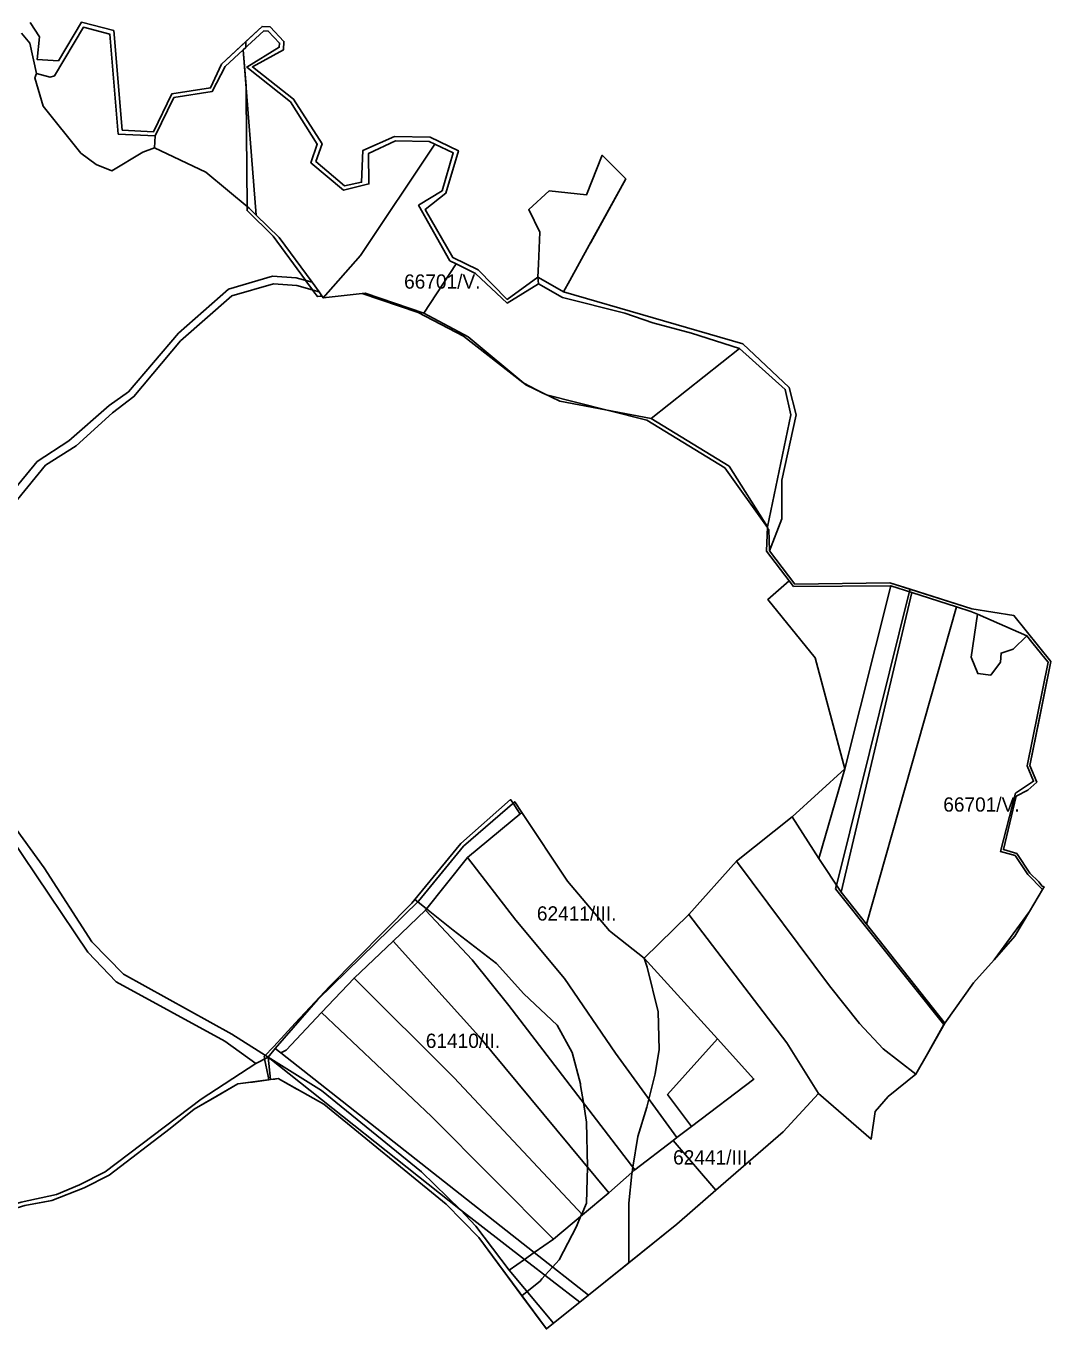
# Model space of a CAD drawing. Extents: x -522079 to -518833, y -1142400 to -1139961.
# Drawn here: x -519191.9 to -518832.8, y -1141827.7 to -1141371.1 of the extents above; entities that cross this region are included whole.
import ezdxf

# ---------------------------------------------------------------- set-up
doc = ezdxf.new("R2010")
doc.units = 0
for name, color, linetype in [('95560013', 7, 'Continuous'), ('95610013', 7, 'Continuous'), ('95620013', 7, 'Continuous'), ('95630013', 7, 'Continuous'), ('95640013', 7, 'Continuous'), ('95660013', 7, 'Continuous')]:
    doc.layers.add(name, color=color, linetype=linetype)

msp = doc.modelspace()

# ---------------------------------------------------------------- linework, layer by layer
at = {"layer": '95560013'}
for points in [[(-519037.2, -1141662.52), (-519020.32, -1141684.47), (-519003.26, -1141704.92), (-518985.35, -1141731.05), (-518963.82, -1141760.65), (-518965.15, -1141761.66), (-518978.59, -1141771.9), (-519022.75, -1141714.32), (-519035.63, -1141698.35), (-519051.93, -1141680.89)], [(-518978.59, -1141771.9), (-518987.69, -1141779.96), (-519033.2, -1141725.1), (-519063.3, -1141691.75), (-519051.93, -1141680.89), (-519035.63, -1141698.35), (-519022.75, -1141714.32)], [(-519063.3, -1141691.75), (-519033.2, -1141725.1), (-518987.69, -1141779.96), (-518996.96, -1141787.68), (-519041.86, -1141739.72), (-519076.93, -1141704.76)], [(-519076.93, -1141704.76), (-519041.86, -1141739.72), (-518996.96, -1141787.68), (-519007.07, -1141796.21), (-519049.77, -1141753.31), (-519088.31, -1141716.77)], [(-519100.73, -1141730.04), (-519088.31, -1141716.77), (-519049.77, -1141753.31), (-519007.07, -1141796.21), (-519013.82, -1141800.95), (-519102.66, -1141730.9)], [(-519034.33, -1141791.67), (-519022.6, -1141807.12), (-519007.06, -1141825.69), (-519009.58, -1141827.71), (-519033.21, -1141795.69), (-519044.72, -1141783.93), (-519087.6, -1141748.94), (-519103.5, -1141739.96), (-519106.29, -1141740.33), (-519107.07, -1141732.42), (-519039.72, -1141785.92)], [(-518978.59, -1141771.9), (-518965.15, -1141761.66), (-518950.14, -1141779.05), (-518963.91, -1141791), (-518994.87, -1141815.89), (-519013.82, -1141800.95), (-519007.07, -1141796.21), (-518996.96, -1141787.68), (-518987.69, -1141779.96)], [(-519039.72, -1141785.92), (-519017.2, -1141803.32), (-519022.6, -1141807.12), (-519034.33, -1141791.67)], [(-519022.6, -1141807.12), (-519017.2, -1141803.32), (-518997.83, -1141818.27), (-519007.06, -1141825.69)]]:
    msp.add_lwpolyline(points, close=True, dxfattribs=at)
at = {"layer": '95610013'}
for points in [[(-519012.53, -1141459.04), (-519012.34, -1141454.52), (-519011.87, -1141443.33), (-519015.74, -1141435.38), (-519008.63, -1141428.83), (-518995.53, -1141430.25), (-518989.97, -1141416.33), (-518981.74, -1141424.63), (-518994.55, -1141447.83), (-519001.41, -1141460.26), (-519003.59, -1141464.2), (-519005.83, -1141462.95)], [(-518906.3, -1141674.57), (-518881.49, -1141569.59), (-518865.88, -1141574.59), (-518897.41, -1141685.82)], [(-518845.18, -1141639.97), (-518850.48, -1141660.34), (-518845.32, -1141661.82), (-518840.87, -1141668.48), (-518835.69, -1141673.66), (-518840.27, -1141681.38), (-518852.72, -1141698.29), (-518859.88, -1141706.38), (-518869.99, -1141720.5), (-518897.41, -1141685.82), (-518865.88, -1141574.59), (-518860.8, -1141576.22), (-518858.5, -1141577.22), (-518860.72, -1141592.27), (-518858.42, -1141598.04), (-518853.84, -1141598.54), (-518850.43, -1141594.07), (-518850.24, -1141590.84), (-518845.96, -1141589.42), (-518841.19, -1141584.77), (-518839.43, -1141586.95), (-518834.47, -1141593.24), (-518833.75, -1141593.98), (-518841.11, -1141630.32), (-518838.85, -1141635.75)], [(-518853.84, -1141598.54), (-518858.42, -1141598.04), (-518860.72, -1141592.27), (-518858.5, -1141577.22), (-518841.19, -1141584.77), (-518845.96, -1141589.42), (-518850.24, -1141590.84), (-518850.43, -1141594.07)], [(-519037.2, -1141662.52), (-519018.14, -1141646.74), (-519002.22, -1141670.75), (-518987.45, -1141688.21), (-518975.25, -1141697.8), (-518949.63, -1141726.06), (-518967.09, -1141745.55), (-518958.75, -1141756.79), (-518963.82, -1141760.65), (-518985.35, -1141731.05), (-519003.26, -1141704.92), (-519020.32, -1141684.47)], [(-518845.39, -1141690.02), (-518852.72, -1141698.29), (-518840.27, -1141681.38)]]:
    msp.add_lwpolyline(points, close=True, dxfattribs=at)
at = {"layer": '95620013'}
for points in [[(-519193.48, -1141373.59), (-519190.53, -1141377.07), (-519188.19, -1141387.74), (-519188.81, -1141389.21), (-519185.95, -1141399.11), (-519172.73, -1141415.6), (-519167.27, -1141419.59), (-519161.79, -1141421.83), (-519150.96, -1141415.24), (-519146.88, -1141413.75), (-519128.84, -1141422.33), (-519113.73, -1141434.94), (-519111.28, -1141437.32), (-519103.24, -1141445.12), (-519091.6, -1141460.78), (-519097.28, -1141459.27), (-519105.52, -1141458.68), (-519120.93, -1141463.32), (-519138.46, -1141478.73), (-519156, -1141499.24), (-519162.77, -1141504.09), (-519176.92, -1141516.46), (-519187.98, -1141523.67), (-519197.16, -1141534.83)], [(-519194.87, -1141536.97), (-519185.11, -1141524.98), (-519174.38, -1141518.14), (-519161.65, -1141506.59), (-519154.09, -1141500.95), (-519137.74, -1141481.36), (-519119.76, -1141465.66), (-519105.2, -1141461.4), (-519097.02, -1141461.95), (-519089.22, -1141464.23), (-519087.76, -1141466.33), (-519073.04, -1141464.69), (-519052.51, -1141471.71), (-519036.96, -1141480), (-519016.8, -1141496.81), (-519004.9, -1141502.52), (-518972.83, -1141508.64), (-518945.58, -1141525.34), (-518932.13, -1141546.59), (-518932.45, -1141555.15), (-518924.52, -1141565.49), (-518931.99, -1141572.05), (-518915.44, -1141592.52), (-518904.97, -1141631.37), (-518923.48, -1141648.24), (-518942.97, -1141663.76), (-518959.67, -1141682.43), (-518975.25, -1141697.8), (-518987.45, -1141688.21), (-519002.22, -1141670.75), (-519018.14, -1141646.74), (-519020.66, -1141642.94), (-519038.58, -1141658.51), (-519054.42, -1141677.83), (-519089.65, -1141712.19), (-519104.58, -1141729.38), (-519107.07, -1141732.42), (-519119.77, -1141724.36), (-519157.76, -1141703.36), (-519168.83, -1141692.07), (-519185.55, -1141666.07), (-519195.4, -1141652.58)], [(-519197.57, -1141654.98), (-519170.28, -1141695.6), (-519160.32, -1141706.01), (-519122.24, -1141726.88), (-519111.34, -1141734.71), (-519130.56, -1141747.22), (-519164.17, -1141772.59), (-519173.18, -1141777.23), (-519181.21, -1141780.54), (-519193.63, -1141783.33)]]:
    msp.add_lwpolyline(points, dxfattribs=at)
for points in [[(-519167.27, -1141419.59), (-519172.73, -1141415.6), (-519185.95, -1141399.11), (-519188.81, -1141389.21), (-519188.19, -1141387.74), (-519183.39, -1141388.93), (-519181.87, -1141388.46), (-519171.77, -1141371.48), (-519162.56, -1141373.86), (-519159.57, -1141408.94), (-519146.7, -1141409.56), (-519146.88, -1141413.75), (-519150.96, -1141415.24), (-519161.79, -1141421.83)], [(-519115.78, -1141379.37), (-519108.63, -1141372.74), (-519107.04, -1141372.83), (-519103.08, -1141377.03), (-519103.16, -1141378.52), (-519114.56, -1141385.44), (-519099.25, -1141397.67), (-519089.83, -1141412.51), (-519092.08, -1141418.96), (-519080.67, -1141428.64), (-519071.77, -1141426.39), (-519071.92, -1141415.76), (-519062.49, -1141411.31), (-519050.68, -1141411.48), (-519048.65, -1141412.42), (-519074.76, -1141451.52), (-519087.76, -1141466.33), (-519089.22, -1141464.23), (-519091.6, -1141460.78), (-519103.24, -1141445.12), (-519111.28, -1141437.32)], [(-519113.73, -1141434.94), (-519128.84, -1141422.33), (-519146.88, -1141413.75), (-519146.7, -1141409.56), (-519140.08, -1141396.13), (-519126.66, -1141393.95), (-519122.09, -1141385.22), (-519115.78, -1141379.37), (-519111.28, -1141437.32)], [(-519048.65, -1141412.42), (-519042.19, -1141415.54), (-519046.13, -1141428.81), (-519054.33, -1141433.88), (-519043.38, -1141453.33), (-519041.21, -1141454.39), (-519052.51, -1141471.71), (-519073.04, -1141464.69), (-519087.76, -1141466.33), (-519074.76, -1141451.52)], [(-518941.87, -1141484.11), (-518972.83, -1141508.64), (-519004.9, -1141502.52), (-519016.8, -1141496.81), (-519036.96, -1141480), (-519052.51, -1141471.71), (-519041.21, -1141454.39), (-519034.35, -1141457.76), (-519023.36, -1141468.17), (-519012.3, -1141461.46), (-519003.93, -1141466.26), (-518982.13, -1141471.67), (-518972.22, -1141475.1), (-518958.68, -1141478.71)], [(-518932.13, -1141546.59), (-518945.58, -1141525.34), (-518972.83, -1141508.64), (-518941.87, -1141484.11), (-518925.88, -1141498.42), (-518923.9, -1141507.34)], [(-518888.92, -1141567.21), (-518904.97, -1141631.37), (-518915.44, -1141592.52), (-518931.99, -1141572.05), (-518924.52, -1141565.49), (-518922.95, -1141567.54)], [(-518906.3, -1141674.57), (-518914.15, -1141662.84), (-518904.97, -1141631.37), (-518888.92, -1141567.21), (-518881.49, -1141569.59)], [(-518904.97, -1141631.37), (-518914.15, -1141662.84), (-518923.48, -1141648.24)], [(-518942.97, -1141663.76), (-518923.48, -1141648.24), (-518914.15, -1141662.84), (-518906.3, -1141674.57), (-518897.41, -1141685.82), (-518869.99, -1141720.5), (-518876.08, -1141731.29), (-518880.1, -1141738.42), (-518891.54, -1141729.55), (-518899.83, -1141720.66), (-518910.37, -1141707.51)], [(-518925.33, -1141727.39), (-518959.67, -1141682.43), (-518942.97, -1141663.76), (-518910.37, -1141707.51), (-518899.83, -1141720.66), (-518891.54, -1141729.55), (-518880.1, -1141738.42), (-518889.83, -1141746.28), (-518894.38, -1141751.49), (-518895.73, -1141761.19), (-518914.26, -1141745.22)], [(-518965.15, -1141761.66), (-518963.82, -1141760.65), (-518958.75, -1141756.79), (-518936.87, -1141740.13), (-518949.63, -1141726.06), (-518975.25, -1141697.8), (-518959.67, -1141682.43), (-518925.33, -1141727.39), (-518914.26, -1141745.22), (-518926.6, -1141758.63), (-518950.14, -1141779.05)], [(-518958.75, -1141756.79), (-518967.09, -1141745.55), (-518949.63, -1141726.06), (-518936.87, -1141740.13)]]:
    msp.add_lwpolyline(points, close=True, dxfattribs=at)
at = {"layer": '95630013'}
msp.add_lwpolyline([(-519190.42, -1141369.81), (-519187.2, -1141374.82), (-519188.01, -1141382.78), (-519180.54, -1141383.29), (-519172.49, -1141369.75), (-519161.16, -1141372.68), (-519158.19, -1141407.51), (-519147.23, -1141408.12), (-519140.85, -1141394.82), (-519127.25, -1141392.73), (-519123.4, -1141384.39), (-519109.18, -1141371.2), (-519106.36, -1141371.37), (-519101.55, -1141376.47), (-519101.7, -1141379.43), (-519112.59, -1141385.36), (-519098.12, -1141396.65), (-519088.18, -1141412.32), (-519090.32, -1141418.48), (-519080.26, -1141427.02), (-519074.35, -1141425.83), (-519073.85, -1141414.66), (-519062.78, -1141409.81), (-519050.33, -1141409.98), (-519040.39, -1141414.74), (-519044.82, -1141429.69), (-519052, -1141435.32), (-519042.3, -1141452.19), (-519033.46, -1141456.53), (-519023.29, -1141466.86), (-519012.53, -1141459.04), (-519012.3, -1141461.46), (-519023.36, -1141468.17), (-519034.35, -1141457.76), (-519041.21, -1141454.39), (-519043.38, -1141453.33), (-519054.33, -1141433.88), (-519046.13, -1141428.81), (-519042.19, -1141415.54), (-519048.65, -1141412.42), (-519050.68, -1141411.48), (-519062.49, -1141411.31), (-519071.92, -1141415.76), (-519071.77, -1141426.39), (-519080.67, -1141428.64), (-519092.08, -1141418.96), (-519089.83, -1141412.51), (-519099.25, -1141397.67), (-519114.56, -1141385.44), (-519103.16, -1141378.52), (-519103.08, -1141377.03), (-519107.04, -1141372.83), (-519108.63, -1141372.74), (-519115.78, -1141379.37), (-519122.09, -1141385.22), (-519126.66, -1141393.95), (-519140.08, -1141396.13), (-519146.7, -1141409.56), (-519159.57, -1141408.94), (-519162.56, -1141373.86), (-519171.77, -1141371.48), (-519181.87, -1141388.46), (-519183.39, -1141388.93), (-519188.19, -1141387.74), (-519190.53, -1141377.07), (-519193.48, -1141373.59)], dxfattribs=at)
msp.add_lwpolyline([(-518841.19, -1141584.77), (-518858.5, -1141577.22), (-518860.8, -1141576.22), (-518865.88, -1141574.59), (-518881.49, -1141569.59), (-518888.92, -1141567.21), (-518922.95, -1141567.54), (-518924.52, -1141565.49), (-518932.45, -1141555.15), (-518932.13, -1141546.59), (-518923.9, -1141507.34), (-518925.88, -1141498.42), (-518941.87, -1141484.11), (-518958.68, -1141478.71), (-518972.22, -1141475.1), (-518982.13, -1141471.67), (-519003.93, -1141466.26), (-519012.3, -1141461.46), (-519012.53, -1141459.04), (-519005.83, -1141462.95), (-519003.59, -1141464.2), (-518940.71, -1141482.48), (-518924.49, -1141497.8), (-518922.06, -1141507.35), (-518927.02, -1141530.23), (-518927.11, -1141543.74), (-518931.43, -1141555), (-518922.51, -1141566.63), (-518889.18, -1141566.18), (-518860.53, -1141575.36), (-518845.76, -1141577.71), (-518832.78, -1141593.74), (-518840.17, -1141630.23), (-518837.74, -1141636.08), (-518840.9, -1141638.87), (-518844.96, -1141640.98), (-518849.41, -1141659.71), (-518844.75, -1141661.05), (-518840.16, -1141667.91), (-518837.05, -1141671.02), (-518835.83, -1141672.48), (-518835.18, -1141672.79), (-518835.69, -1141673.66), (-518840.87, -1141668.48), (-518845.32, -1141661.82), (-518850.48, -1141660.34), (-518845.18, -1141639.97), (-518838.85, -1141635.75), (-518841.11, -1141630.32), (-518833.75, -1141593.98), (-518834.47, -1141593.24), (-518839.43, -1141586.95)], close=True, dxfattribs=at)
at = {"layer": '95640013'}
msp.add_lwpolyline([(-519197.16, -1141534.83), (-519187.98, -1141523.67), (-519176.92, -1141516.46), (-519162.77, -1141504.09), (-519156, -1141499.24), (-519138.46, -1141478.73), (-519120.93, -1141463.32), (-519105.52, -1141458.68), (-519097.28, -1141459.27), (-519091.6, -1141460.78), (-519089.22, -1141464.23), (-519097.02, -1141461.95), (-519105.2, -1141461.4), (-519119.76, -1141465.66), (-519137.74, -1141481.36), (-519154.09, -1141500.95), (-519161.65, -1141506.59), (-519174.38, -1141518.14), (-519185.11, -1141524.98), (-519194.87, -1141536.97)], dxfattribs=at)
for points in [[(-519215.97, -1141644.42), (-519234.03, -1141639.34), (-519247.24, -1141637.55), (-519267.72, -1141635.03), (-519278.79, -1141629.39), (-519283.88, -1141624.46), (-519281.83, -1141620.82), (-519276.07, -1141627.44), (-519266.93, -1141631.65), (-519236.73, -1141634.83), (-519229.49, -1141636.68), (-519214.22, -1141641.4), (-519195.4, -1141652.58), (-519185.55, -1141666.07), (-519168.83, -1141692.07), (-519157.76, -1141703.36), (-519119.77, -1141724.36), (-519107.07, -1141732.42), (-519111.34, -1141734.71), (-519122.24, -1141726.88), (-519160.32, -1141706.01), (-519170.28, -1141695.6), (-519197.57, -1141654.98)], [(-519100.73, -1141730.04), (-519102.66, -1141730.9), (-519104.58, -1141729.38), (-519089.65, -1141712.19), (-519054.42, -1141677.83), (-519038.58, -1141658.51), (-519020.66, -1141642.94), (-519018.14, -1141646.74), (-519037.2, -1141662.52), (-519051.93, -1141680.89), (-519063.3, -1141691.75), (-519076.93, -1141704.76), (-519088.31, -1141716.77)], [(-519053.38, -1141772.67), (-519088.35, -1141744.1), (-519107.07, -1141732.42), (-519104.58, -1141729.38), (-519102.66, -1141730.9), (-519013.82, -1141800.95), (-519017.2, -1141803.32), (-519039.72, -1141785.92)], [(-519192.31, -1141784.44), (-519205.85, -1141788.49), (-519209.88, -1141790.38), (-519211, -1141789.08), (-519208.31, -1141787.64), (-519193.63, -1141783.33), (-519181.21, -1141780.54), (-519173.18, -1141777.23), (-519164.17, -1141772.59), (-519130.56, -1141747.22), (-519111.34, -1141734.71), (-519107.07, -1141732.42), (-519106.29, -1141740.33), (-519117.64, -1141741.85), (-519132.98, -1141750.7), (-519141.38, -1141757.45), (-519162.82, -1141773.79), (-519171.52, -1141778.29), (-519182.83, -1141782.69)], [(-519053.38, -1141772.67), (-519039.72, -1141785.92), (-519107.07, -1141732.42), (-519088.35, -1141744.1)], [(-518994.87, -1141815.89), (-518997.83, -1141818.27), (-519017.2, -1141803.32), (-519013.82, -1141800.95)]]:
    msp.add_lwpolyline(points, close=True, dxfattribs=at)
at = {"layer": '95660013'}
msp.add_lwpolyline([(-519190.42, -1141369.81), (-519187.2, -1141374.82), (-519188.01, -1141382.78), (-519180.54, -1141383.29), (-519172.49, -1141369.75), (-519161.16, -1141372.68), (-519158.19, -1141407.51), (-519147.23, -1141408.12), (-519140.85, -1141394.82), (-519127.25, -1141392.73), (-519123.4, -1141384.39), (-519114.91, -1141376.51), (-519114.89, -1141378.55), (-519115.78, -1141379.37), (-519114.79, -1141392.16), (-519114.76, -1141395.66), (-519114.45, -1141434.34), (-519114.44, -1141435.73), (-519105.32, -1141444.7), (-519093.99, -1141460.14), (-519093.82, -1141460.38), (-519091.51, -1141463.56), (-519091.05, -1141464.19), (-519089.82, -1141465.88), (-519088.81, -1141465.79), (-519088.18, -1141465.73), (-519087.76, -1141466.33), (-519074.1, -1141464.81), (-519054.45, -1141471.42), (-519038.62, -1141479.75), (-519017.88, -1141496.05), (-519017.44, -1141496.27), (-519011.01, -1141499.58), (-519009.72, -1141500.25), (-519009.51, -1141500.31), (-518988.31, -1141505.68), (-518974.38, -1141509.22), (-518947.06, -1141525.93), (-518932.14, -1141546.87), (-518931.94, -1141547.15), (-518931.68, -1141547.51), (-518931.43, -1141555), (-518922.51, -1141566.63), (-518889.18, -1141566.18), (-518882.12, -1141568.44), (-518882.2, -1141568.75), (-518882.42, -1141569.64), (-518906.77, -1141667.62), (-518907.9, -1141672.18), (-518908.23, -1141673.5), (-518881.36, -1141707.08), (-518870.25, -1141720.96), (-518876.08, -1141731.29), (-518880.1, -1141738.42), (-518889.83, -1141746.28), (-518894.38, -1141751.49), (-518895.73, -1141761.19), (-518914.26, -1141745.22), (-518926.6, -1141758.63), (-518950.14, -1141779.05), (-518965.15, -1141761.66), (-518963.82, -1141760.65), (-518958.75, -1141756.79), (-518967.09, -1141745.55), (-518949.63, -1141726.06), (-518975.25, -1141697.8), (-518987.45, -1141688.21), (-519002.22, -1141670.75), (-519018.14, -1141646.74), (-519018.79, -1141647.28), (-519019.83, -1141645.67), (-519021.25, -1141643.45), (-519022.09, -1141642.15), (-519039.51, -1141657.59), (-519049.19, -1141669.31), (-519055.71, -1141677.2), (-519056.76, -1141678.48), (-519085.6, -1141707.64), (-519097.6, -1141720.57), (-519105.12, -1141728.66), (-519105.58, -1141729.16), (-519108.03, -1141731.81), (-519108.23, -1141732.02), (-519108.46, -1141732.26), (-519108.37, -1141732.68), (-519108.29, -1141733.07), (-519107.07, -1141739.1), (-519106.85, -1141740.41), (-519112.49, -1141741.16), (-519114, -1141741.36), (-519117.64, -1141741.85), (-519125.57, -1141746.42), (-519129.17, -1141748.5), (-519132.98, -1141750.7), (-519141.38, -1141757.45), (-519162.82, -1141773.79), (-519171.52, -1141778.29), (-519182.83, -1141782.69), (-519185.92, -1141783.26), (-519192.31, -1141784.44)], dxfattribs=at)
for points in [[(-519109.18, -1141371.2), (-519106.36, -1141371.37), (-519101.55, -1141376.47), (-519101.7, -1141379.43), (-519112.59, -1141385.36), (-519098.12, -1141396.65), (-519088.18, -1141412.32), (-519090.32, -1141418.48), (-519080.26, -1141427.02), (-519074.35, -1141425.83), (-519073.85, -1141414.66), (-519062.78, -1141409.81), (-519050.33, -1141409.98), (-519040.39, -1141414.74), (-519044.82, -1141429.69), (-519052, -1141435.32), (-519042.3, -1141452.19), (-519033.46, -1141456.53), (-519023.29, -1141466.86), (-519012.53, -1141459.04), (-519012.34, -1141454.52), (-519011.87, -1141443.33), (-519015.74, -1141435.38), (-519008.63, -1141428.83), (-518995.53, -1141430.25), (-518989.97, -1141416.33), (-518981.74, -1141424.63), (-518994.04, -1141446.9), (-518994.26, -1141447.3), (-518994.55, -1141447.83), (-519001.41, -1141460.26), (-519003.59, -1141464.2), (-518940.71, -1141482.48), (-518924.49, -1141497.8), (-518922.06, -1141507.35), (-518927.02, -1141530.23), (-518927.11, -1141543.74), (-518931.43, -1141555), (-518931.68, -1141547.51), (-518931.94, -1141547.15), (-518932.14, -1141546.87), (-518947.06, -1141525.93), (-518974.38, -1141509.22), (-518988.31, -1141505.68), (-519009.51, -1141500.31), (-519009.72, -1141500.25), (-519011.01, -1141499.58), (-519017.44, -1141496.27), (-519017.88, -1141496.05), (-519038.62, -1141479.75), (-519054.45, -1141471.42), (-519074.1, -1141464.81), (-519087.76, -1141466.33), (-519088.18, -1141465.73), (-519088.81, -1141465.79), (-519089.82, -1141465.88), (-519091.05, -1141464.19), (-519091.51, -1141463.56), (-519093.82, -1141460.38), (-519093.99, -1141460.14), (-519105.32, -1141444.7), (-519114.44, -1141435.73), (-519114.45, -1141434.34), (-519114.76, -1141395.66), (-519114.79, -1141392.16), (-519115.78, -1141379.37), (-519114.89, -1141378.55), (-519114.91, -1141376.51)], [(-518832.78, -1141593.74), (-518833.26, -1141596.09), (-518837.06, -1141614.85), (-518840.17, -1141630.23), (-518837.74, -1141636.08), (-518840.9, -1141638.87), (-518844.96, -1141640.98), (-518849.41, -1141659.71), (-518844.75, -1141661.05), (-518840.16, -1141667.91), (-518837.05, -1141671.02), (-518835.83, -1141672.48), (-518835.18, -1141672.79), (-518835.69, -1141673.66), (-518840.27, -1141681.38), (-518845.39, -1141690.02), (-518852.72, -1141698.29), (-518859.88, -1141706.38), (-518869.99, -1141720.5), (-518870.25, -1141720.96), (-518881.36, -1141707.08), (-518908.23, -1141673.5), (-518907.9, -1141672.18), (-518906.77, -1141667.62), (-518882.42, -1141569.64), (-518882.2, -1141568.75), (-518882.12, -1141568.44), (-518860.53, -1141575.36), (-518845.76, -1141577.71)], [(-519009.65, -1141827.61), (-519018.17, -1141816.07), (-519016.34, -1141814.6), (-519011.8, -1141810.95), (-519011.11, -1141810.19), (-519009.96, -1141808.91), (-519007.37, -1141806.04), (-519005.08, -1141803.51), (-518999.07, -1141791.8), (-518997.47, -1141788.11), (-518997.18, -1141787.44), (-518995.54, -1141783.65), (-518995.18, -1141770.9), (-518995.54, -1141755.28), (-518996.62, -1141748.38), (-518997.57, -1141742.39), (-518997.66, -1141741.8), (-519000.49, -1141730.81), (-519005.79, -1141721.24), (-519017.45, -1141710.24), (-519027, -1141699.6), (-519042.2, -1141687.9), (-519051.59, -1141680.46), (-519054.64, -1141678.04), (-519055.71, -1141677.2), (-519049.19, -1141669.31), (-519039.51, -1141657.59), (-519022.09, -1141642.15), (-519021.25, -1141643.45), (-519019.83, -1141645.67), (-519018.79, -1141647.28), (-519018.14, -1141646.74), (-519002.22, -1141670.75), (-518987.45, -1141688.21), (-518975.25, -1141697.8), (-518975.03, -1141698.5), (-518974.24, -1141700.97), (-518970.44, -1141716.62), (-518970.09, -1141729.75), (-518971.5, -1141738.26), (-518973.65, -1141747.14), (-518974.33, -1141749.96), (-518977.51, -1141760.25), (-518979.25, -1141771.03), (-518979.53, -1141772.73), (-518979.63, -1141773.36), (-518980.69, -1141783.65), (-518980.69, -1141792.87), (-518980.69, -1141800.95), (-518980.69, -1141803.93), (-518980.69, -1141804.49), (-518994.87, -1141815.89), (-518997.83, -1141818.27), (-519007.06, -1141825.69), (-519009.58, -1141827.71)], [(-519103.5, -1141739.96), (-519104.73, -1141740.12), (-519106.29, -1141740.33), (-519106.85, -1141740.41), (-519107.07, -1141739.1), (-519108.29, -1141733.07), (-519108.37, -1141732.68), (-519108.46, -1141732.26), (-519108.23, -1141732.02), (-519108.03, -1141731.81), (-519105.58, -1141729.16), (-519105.12, -1141728.66), (-519097.6, -1141720.57), (-519085.6, -1141707.64), (-519056.76, -1141678.48), (-519055.71, -1141677.2), (-519054.64, -1141678.04), (-519051.59, -1141680.46), (-519042.2, -1141687.9), (-519027, -1141699.6), (-519017.45, -1141710.24), (-519005.79, -1141721.24), (-519000.49, -1141730.81), (-518997.66, -1141741.8), (-518997.57, -1141742.39), (-518996.62, -1141748.38), (-518995.54, -1141755.28), (-518995.18, -1141770.9), (-518995.54, -1141783.65), (-518997.18, -1141787.44), (-518997.47, -1141788.11), (-518999.07, -1141791.8), (-519005.08, -1141803.51), (-519007.37, -1141806.04), (-519009.96, -1141808.91), (-519011.11, -1141810.19), (-519011.8, -1141810.95), (-519016.34, -1141814.6), (-519018.17, -1141816.07), (-519033.21, -1141795.69), (-519044.72, -1141783.93), (-519087.6, -1141748.94), (-519096.93, -1141743.67), (-519096.96, -1141743.65)], [(-518952.9, -1141781.45), (-518963.91, -1141791), (-518980.69, -1141804.49), (-518980.69, -1141803.93), (-518980.69, -1141800.95), (-518980.69, -1141792.87), (-518980.69, -1141783.65), (-518979.63, -1141773.36), (-518979.53, -1141772.73), (-518979.25, -1141771.03), (-518977.51, -1141760.25), (-518974.33, -1141749.96), (-518973.65, -1141747.14), (-518971.5, -1141738.26), (-518970.09, -1141729.75), (-518970.44, -1141716.62), (-518974.24, -1141700.97), (-518975.03, -1141698.5), (-518975.25, -1141697.8), (-518949.63, -1141726.06), (-518967.09, -1141745.55), (-518958.75, -1141756.79), (-518963.82, -1141760.65), (-518965.15, -1141761.66), (-518950.14, -1141779.05), (-518952.9, -1141781.44)]]:
    msp.add_lwpolyline(points, close=True, dxfattribs=at)

# ---------------------------------------------------------------- texts
for s, rotation, p in [('66701/V.', 360, (-519059.42, -1141463.1)), ('66701/V.', 0, (-518870.51, -1141646.4)), ('62411/III.', 0, (-519012.9, -1141684.59)), ('61410/II.', 0, (-519051.82, -1141729.21)), ('62441/III.', 360, (-518965.16, -1141770.08))]:
    msp.add_text(s, height=5, rotation=rotation, dxfattribs=at).set_placement(p)

doc.saveas('drawing.dxf')
